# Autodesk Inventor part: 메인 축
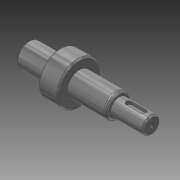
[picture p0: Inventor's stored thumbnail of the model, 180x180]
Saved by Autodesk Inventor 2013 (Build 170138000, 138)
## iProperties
Created: 2016-04
Part Number: 메인 축
Document SubType Name: Modeling
Designer: mdu
Density: 7.86 g/cm^3
Mass: 230.24 g
Surface Area: 74.3518 cm^2
Volume: 29.2926 cm^3
Material: 강철, 연강
Author: mdu
Revision Number: 1
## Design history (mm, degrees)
sketch "스케치1"
  geometry: L1 (10.497, -57.5)-(97.497, -57.5); L2 (10.497, -66)-(32.497, -66); L3 (32.497, -72.5)-(46.5, -72.5); L4 (46.5, -66)-(74.497, -66); L5 (97.497, -63.5)-(97.497, -57.5); L6 (10.497, -66)-(10.497, -57.5); L7 (46.5, -69.749)-(46.5, -45.251) reference; L8 (46.5, -72.5)-(46.5, -66); L9 (32.497, -72.5)-(32.497, -66); L10 (32.497, -35)-(32.497, -80) reference; L11 (97.497, -63.5)-(74.497, -63.5); L12 (74.497, -63.5)-(74.497, -66); 3 further points
  constraints: 20 end point, 4 perpendicular, 3 point on line, 2 parallel, 1 collinear, 1 horizontal, 1 midpoint
  dimensions: "d0" = 17 diameter of L4 L1; "d1" = 30 diameter of L3 L1; "d2" = 22 distance of L2.start L2.end; "d5" = 17 diameter of L2 L1; "d19" = 65 distance between parallel lines of L5 L9; "d21" = 50.99692 distance between parallel lines of L5 L8 (derived); "d22" = 23 distance between parallel lines of L5 L12; "d23" = 12 diameter of L11 L1
revolve "회전1" sketch "스케치1" stored, may be unused: angle "d4" = 90 deg
chamfer "모따기1" distance "d6" = 1; stored, may be unused: second distance "d7" = 2, angle "d8" = 45 deg
node "작업 평면1"
sketch "스케치2"
  geometry: L1 (10.497, -65)-(10.497, -50) reference; L2 (16.997, -55)-(25.997, -55); L3 (25.997, -60)-(16.997, -60); A1 r 2.5 centre (25.997, -57.5) between (25.997, -60) and (25.997, -55); A2 r 2.5 centre (16.997, -57.5) between (16.997, -55) and (16.997, -60); 2 further points
  constraints: 4 end point, 4 point on circle, 4 tangent, 2 centre point, 1 horizontal alignment, 1 midpoint, 1 parallel, 1 perpendicular
  dimensions: "d9" = 5 distance between parallel lines of L3 L2; "d10" = 14 dimension on A1 A2; "d11" = 4 distance edge to line of A2 L1
extrude "돌출1" cut sketch "스케치2" distance "d12" = 3; taper "d13" = 0 deg
node "작업 평면2"
sketch "스케치3"
  geometry: L1 (91.497, -55.5)-(81.497, -55.5); L2 (81.497, -59.5)-(91.497, -59.5); L3 (97.497, -52.5)-(97.497, -62.5) reference; A1 r 2 centre (81.497, -57.5) between (81.497, -55.5) and (81.497, -59.5); A2 r 2 centre (91.497, -57.5) between (91.497, -59.5) and (91.497, -55.5); 4 further points
  constraints: 4 end point, 4 point on circle, 4 tangent, 2 centre point, 2 horizontal, 2 point on line, 1 horizontal alignment, 1 midpoint, 1 vertical alignment
  dimensions: "d32" = 14 dimension on A2 A1; "d34" = 4 distance edge to line of A2 L3; "d35" = 4 distance between parallel lines of L2 L1
extrude "돌출2" cut sketch "스케치3" distance "d16" = 2.5; taper "d17" = 0 deg
sketch "스케치4"
  geometry: L1 (74.497, -50.05)-(72.678, -49); L2 (74.497, -49)-(46.5, -49) reference; L3 (74.497, -49)-(74.497, -66) reference; L4 (74.497, -66)-(46.5, -66) reference; L5 (74.497, -57.5)-(60.711, -57.5); 1 further point
  constraints: 4 end point, 2 point on line, 1 midpoint, 1 parallel
  dimensions: "d24" = 14.9 diameter of L1.start L5; "d26" = 30 deg angle of L2 L1
revolve "회전2" sketch "스케치4" stored, may be unused: angle "d28" = 90 deg
fillet "모깎기1" dims "d29" = 1
fillet "모깎기2" dims "d30" = 2
hole "구멍1" diameter "d38" = 3.242; stored, may be unused: countersink angle "d42" = 90 deg, drill point angle "d44" = 118 deg; dims "d39" = 8, "d40" = 4, "d41" = 2, "d43" = 10, "d45" = 10, "d46" = 10
node "솔리드1"
node "참조4"
node "참조5"
other parameters: "d20" = 6, "d47" = -8.5
